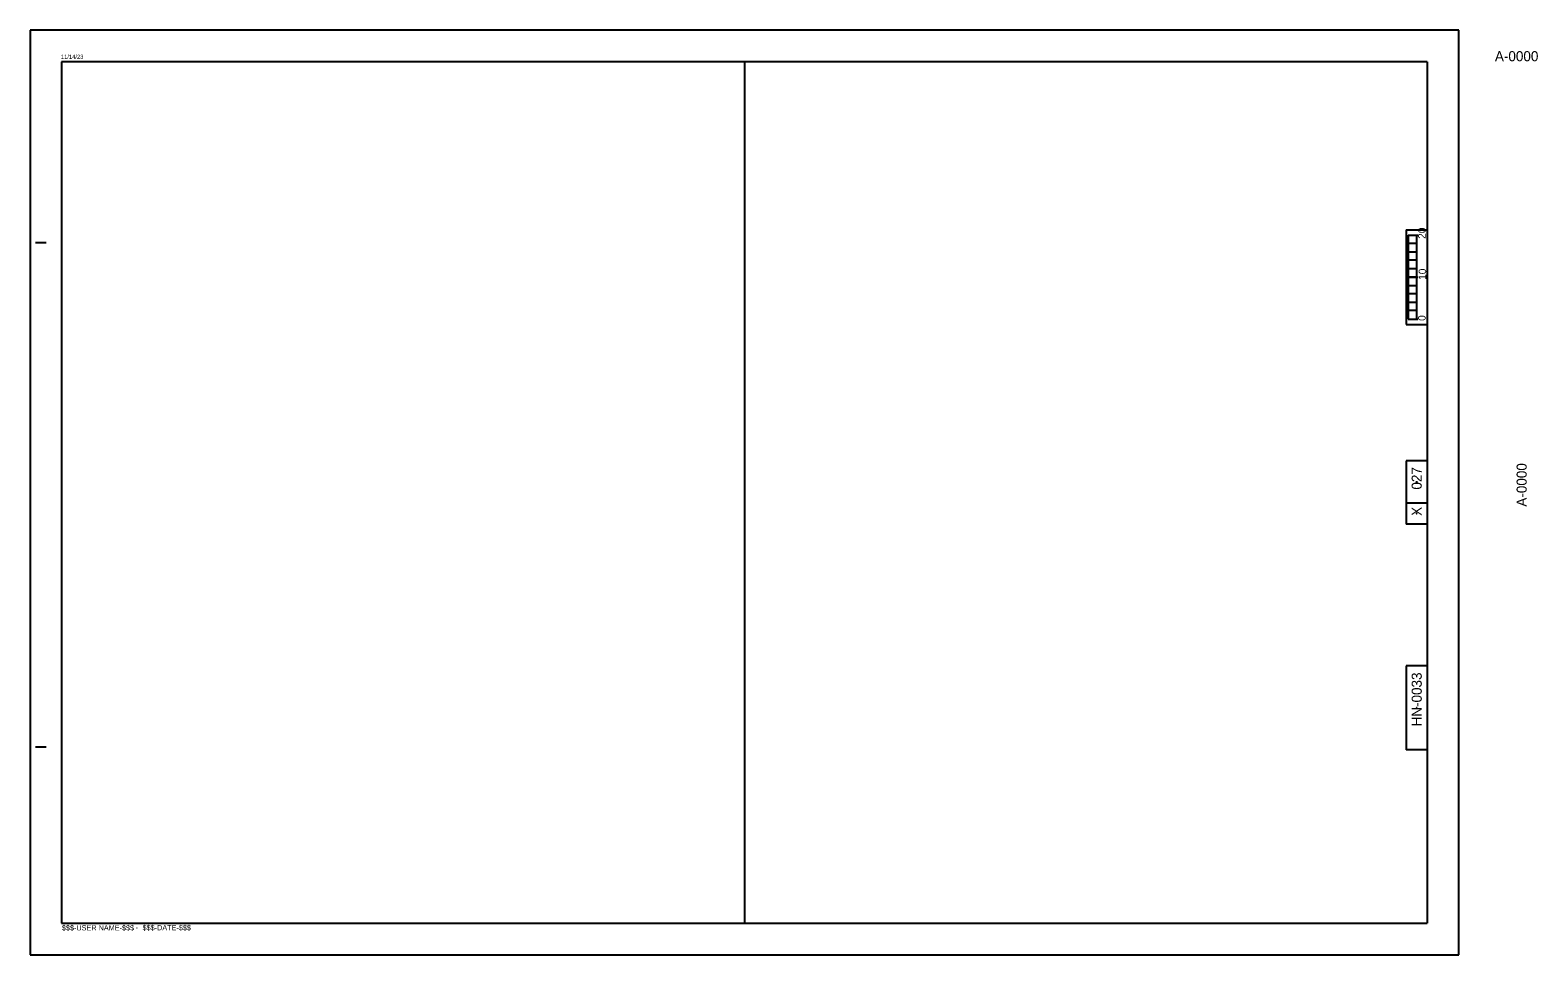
# Model space of a CAD drawing. Extents: x -2.69 to 2.99, y 0 to 1.83.
# Drawn here: x 0 to 2.99, y 0 to 1.833 of the extents above; entities that cross this region are included whole.
import ezdxf

# ---------------------------------------------------------------- set-up
doc = ezdxf.new("R2010")
doc.units = 0
for name, color, linetype in [('P_NCDOT_XS_Sheet_Alignment_Station_Label', 7, 'Continuous'), ('P_NCDOT_XS_Sheet_Grid_Border', 7, 'Continuous'), ('Sheet_Grid_Major', 7, 'Continuous'), ('Sheet_Grid_Middle', 7, 'Continuous'), ('Sheet_Grid_Minor', 7, 'Continuous')]:
    doc.layers.add(name, color=color, linetype=linetype)

msp = doc.modelspace()

# ---------------------------------------------------------------- linework, layer by layer
at = {"layer": 'P_NCDOT_XS_Sheet_Alignment_Station_Label'}
for p, q in [((2.7332, 1.4272), (2.7521, 1.4272)), ((2.7332, 1.4272), (2.7332, 1.2605)), ((2.7416, 1.4272), (2.7503, 1.4272)), ((2.7499, 1.4272), (2.7499, 1.2605)), ((2.7332, 1.3438), (2.7521, 1.3438)), ((2.7332, 1.2605), (2.7521, 1.2605)), ((2.7416, 1.2605), (2.7503, 1.2605))]:
    msp.add_line(p, q, dxfattribs=at)
for points in [[(2.7332, 1.4272), (2.7499, 1.4272), (2.7499, 1.4105), (2.7332, 1.4105)], [(2.7332, 1.3938), (2.7499, 1.3938), (2.7499, 1.3772), (2.7332, 1.3772)], [(2.7332, 1.3605), (2.7499, 1.3605), (2.7499, 1.3438), (2.7332, 1.3438)], [(2.7332, 1.3272), (2.7499, 1.3272), (2.7499, 1.3105), (2.7332, 1.3105)], [(2.7332, 1.2938), (2.7499, 1.2938), (2.7499, 1.2772), (2.7332, 1.2772)]]:
    msp.add_lwpolyline(points, close=True, dxfattribs=at)
at = {"layer": 'Sheet_Grid_Major'}
for p, q in [((2.8333, 1.8333), (0, 1.8333)), ((0, 1.8333), (0, 0)), ((2.8333, 0), (2.8333, 1.8333)), ((1.4167, 1.7708), (1.4166, 0.0625)), ((0, 0), (2.8333, 0))]:
    msp.add_line(p, q, dxfattribs=at)
for centre in [(2.7499, 1.3437), (2.7499, 0.9375), (2.7499, 0.875), (2.75, 0.4897)]:
    msp.add_circle(centre, 0.0001, dxfattribs=at)
at = {"layer": 'Sheet_Grid_Minor'}
for p, q in [((0.0625, 1.7708), (0.0625, 0.0625)), ((2.7708, 1.7708), (0.0625, 1.7708)), ((0.1027, 1.7844), (0.1027, 1.7844)), ((2.7708, 1.7708), (2.7708, 0.0625)), ((2.7292, 1.4375), (2.7292, 1.25)), ((2.7292, 1.4375), (2.7708, 1.4375)), ((0.0108, 1.4125), (0.0317, 1.4126)), ((2.7292, 1.25), (2.7708, 1.25)), ((2.7292, 0.9792), (2.7292, 0.8542)), ((2.7708, 0.9792), (2.7292, 0.9792)), ((2.7708, 0.8958), (2.7292, 0.8958)), ((2.7708, 0.8542), (2.7292, 0.8542)), ((2.7292, 0.5729), (2.7292, 0.4062)), ((2.7708, 0.5729), (2.7292, 0.5729)), ((0.0109, 0.4125), (0.0317, 0.4125)), ((2.7708, 0.4062), (2.7292, 0.4062)), ((0.0625, 0.0625), (2.7708, 0.0625))]:
    msp.add_line(p, q, dxfattribs=at)

# ---------------------------------------------------------------- texts
at = {"layer": 'P_NCDOT_XS_Sheet_Alignment_Station_Label'}
for s, p in [('20', (2.7678, 1.4196)), ('10', (2.7688, 1.3382)), ('0', (2.7677, 1.2569))]:
    msp.add_text(s, height=0.015, rotation=90, dxfattribs=at).set_placement(p)
at = {"layer": 'P_NCDOT_XS_Sheet_Grid_Border'}
for s, p in [('027', (2.7599, 0.9224)), ('X', (2.7599, 0.8704))]:
    msp.add_text(s, height=0.02, rotation=90, dxfattribs=at).set_placement(p)
at = {"layer": 'Sheet_Grid_Middle'}
msp.add_text('A-0000', height=0.02, dxfattribs=at).set_placement((2.9051, 1.7717))
for s, p in [('A-0000', (2.9681, 0.8886)), ('HN-0033', (2.76, 0.4528))]:
    msp.add_text(s, height=0.02, rotation=90, dxfattribs=at).set_placement(p)
at = {"layer": 'Sheet_Grid_Minor'}
msp.add_text('11/14/23', height=0.00833, rotation=0, dxfattribs=at).set_placement((0.0609, 1.7764))
for s, height, p in [('$$$-DATE-$$$', 0.010417, (0.223, 0.0486)), ('$$$-USER NAME-$$$', 0.010417, (0.063, 0.0484)), ('-', 0.0104, (0.2093, 0.0494))]:
    msp.add_text(s, height=height, dxfattribs=at).set_placement(p)

doc.saveas('drawing.dxf')
